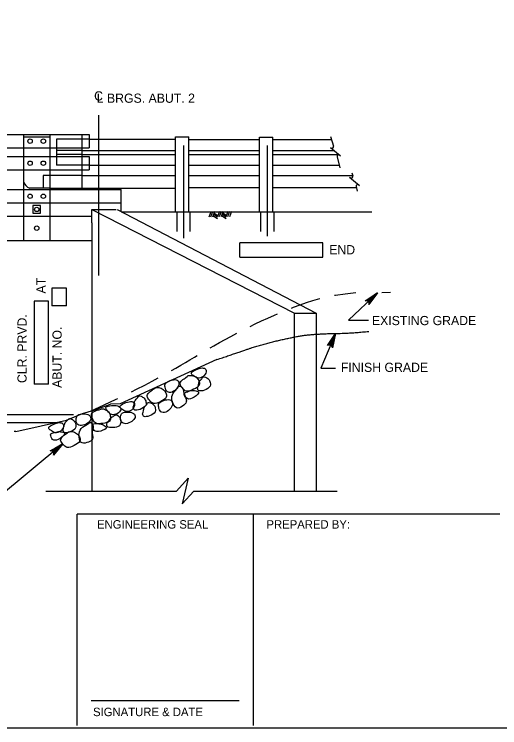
# Model space of a CAD drawing. Extents: x -8 to 75, y -110 to 0.
# Drawn here: x 11.66 to 18.01, y -65.25 to -55.91 of the extents above; entities that cross this region are included whole.
import ezdxf

# ---------------------------------------------------------------- set-up
doc = ezdxf.new("R2010")
doc.units = 0
for name, color, linetype in [('1', 7, 'Continuous'), ('10', 7, 'Continuous'), ('3', 7, 'Continuous'), ('4', 7, 'Continuous'), ('63', 7, 'Continuous'), ('8', 7, 'Continuous')]:
    doc.layers.add(name, color=color, linetype=linetype)

# ---------------------------------------------------------------- blocks, each defined once
blk = doc.blocks.new('F10000')
at = {"layer": '63'}
blk.add_lwpolyline([(-0.03125, -0.03125), (0.03125, -0.03125), (0.03125, 0.03125), (-0.03125, 0.03125)], close=True, dxfattribs=at)

msp = doc.modelspace()

# ---------------------------------------------------------------- linework, layer by layer
at = {"layer": '1'}
msp.add_lwpolyline([(1.75, -65.25), (33.25, -65.25), (33.25, -44.75), (1.75, -44.75)], close=True, dxfattribs=at)
at = {"layer": '3'}
for p, q in [((5.5604, -57.4883), (12.6373, -57.4883)), ((11.7806, -57.4883), (11.7806, -58.8724)), ((12.1266, -57.4883), (12.1266, -58.8724)), ((12.5421, -57.4883), (12.5421, -57.6612)), ((12.6373, -57.4883), (12.6373, -57.6612)), ((11.7806, -57.5171), (12.1266, -57.5171)), ((12.6373, -57.5493), (12.2133, -57.5493)), ((12.2133, -57.5493), (12.2133, -57.8887)), ((12.6373, -57.5493), (13.7701, -57.5493)), ((13.7701, -57.5187), (13.9431, -57.5187)), ((13.7701, -58.4975), (13.7701, -57.5187)), ((13.9431, -58.4975), (13.9431, -57.5187)), ((13.9431, -57.5507), (14.8658, -57.5507)), ((14.8658, -57.5218), (15.0388, -57.5218)), ((14.8658, -58.4975), (14.8658, -57.5218)), ((15.0388, -58.4975), (15.0388, -57.5218)), ((15.0388, -57.5507), (15.8068, -57.5507)), ((15.7952, -57.5147), (15.8358, -57.6407)), ((10.2234, -57.6612), (11.7806, -57.6612)), ((11.7806, -57.6612), (12.1266, -57.6612)), ((12.1266, -57.6612), (12.6373, -57.6612)), ((12.5421, -57.6953), (12.2133, -57.6953)), ((12.5421, -57.6612), (12.5421, -57.7767)), ((12.5421, -57.6953), (13.7701, -57.6953)), ((13.8709, -57.6324), (13.8709, -58.8434)), ((13.9431, -57.6953), (14.8658, -57.6953)), ((14.9667, -57.6324), (14.9667, -58.8182)), ((15.0388, -57.6953), (15.8396, -57.6953)), ((15.7932, -57.6562), (15.9238, -57.7658)), ((10.2234, -57.7767), (11.7806, -57.7767)), ((11.7806, -57.7767), (12.1266, -57.7767)), ((12.1266, -57.7767), (12.6373, -57.7767)), ((12.5421, -57.7473), (12.2133, -57.7473)), ((12.5421, -57.7473), (13.7701, -57.7473)), ((12.5421, -57.7767), (12.5421, -57.9497)), ((12.6373, -57.7767), (12.6373, -57.9497)), ((13.9431, -57.7473), (14.8658, -57.7473)), ((15.0388, -57.7473), (15.9017, -57.7473)), ((15.8805, -57.7794), (15.9167, -57.924)), ((10.2234, -57.9497), (11.7806, -57.9497)), ((11.7806, -57.9497), (12.1266, -57.9497)), ((12.1266, -57.9497), (12.6373, -57.9497)), ((12.6373, -57.8887), (12.2133, -57.8887)), ((12.5421, -57.9497), (12.5421, -58.1882)), ((12.6373, -57.8887), (13.7701, -57.8887)), ((13.9431, -57.8887), (14.8658, -57.8887)), ((15.0388, -57.8887), (15.9078, -57.8887)), ((12.5421, -58.0253), (12.0395, -58.0253)), ((12.0395, -58.0253), (12.0395, -58.1882)), ((12.5421, -58.0253), (13.7701, -58.0253)), ((13.9431, -58.0253), (14.8658, -58.0253)), ((15.0388, -58.0253), (16.0841, -58.0253)), ((16.0427, -58.0451), (16.1733, -58.1547)), ((16.0727, -57.9899), (16.0854, -58.0296)), ((10.2234, -58.2092), (11.7806, -58.2092)), ((11.7806, -58.2092), (12.1266, -58.2092)), ((12.1267, -58.1882), (11.8633, -58.1882)), ((12.1264, -58.1882), (13.7701, -58.1882)), ((12.1266, -58.2092), (13.0586, -58.2092)), ((13.0586, -58.4975), (13.0586, -58.2092)), ((14.8658, -58.1836), (13.9431, -58.1836)), ((16.1339, -58.1836), (15.0388, -58.1836)), ((16.1301, -58.1683), (16.1452, -58.2287)), ((10.2234, -58.3822), (11.7806, -58.3822)), ((11.7806, -58.3822), (12.1266, -58.3822)), ((12.1266, -58.3822), (13.0586, -58.3822)), ((12.6747, -58.6417), (12.6747, -58.4687)), ((12.6747, -58.4687), (15.3228, -59.8239)), ((12.6747, -58.6417), (12.6747, -58.4687)), ((12.6747, -58.4687), (12.9918, -58.4687)), ((13.0032, -58.4687), (15.6082, -59.8239)), ((13.0586, -58.4975), (16.3372, -58.4975)), ((13.7844, -58.4975), (13.7844, -58.757)), ((13.9574, -58.4975), (13.9574, -58.757)), ((14.2294, -58.4975), (14.2027, -58.5677)), ((14.2513, -58.4972), (14.2247, -58.5674)), ((14.2768, -58.4967), (14.2502, -58.567)), ((14.265, -58.5277), (14.3167, -58.5634)), ((14.2715, -58.5105), (14.3231, -58.5463)), ((14.3419, -58.4967), (14.3157, -58.566)), ((14.3638, -58.4966), (14.3376, -58.5656)), ((14.3892, -58.4963), (14.3631, -58.5652)), ((14.3774, -58.5272), (14.429, -58.563)), ((14.3838, -58.5101), (14.4355, -58.5459)), ((14.4543, -58.4963), (14.4281, -58.5656)), ((14.4762, -58.4962), (14.45, -58.5652)), ((14.5016, -58.496), (14.4755, -58.5648)), ((14.8802, -58.4975), (14.8802, -58.757)), ((15.0532, -58.4975), (15.0532, -58.757)), ((10.2234, -58.5552), (11.7806, -58.5552)), ((11.7806, -58.5552), (12.1266, -58.5552)), ((12.1266, -58.5552), (12.6747, -58.5552)), ((14.2582, -58.5456), (14.3182, -58.5872)), ((14.3706, -58.5452), (14.4306, -58.5867)), ((12.6747, -58.6417), (12.6747, -61.1017)), ((5.5232, -58.8724), (12.6747, -58.8724)), ((16.4092, -59.5601), (16.0298, -59.9173)), ((15.3228, -59.8239), (15.6082, -59.8239)), ((15.3228, -60.1378), (15.3228, -59.8239)), ((15.6082, -59.8239), (15.6082, -60.1017)), ((16.0298, -59.9173), (16.2937, -59.9173)), ((15.6082, -60.1017), (15.6082, -62.1527)), ((15.8586, -60.0913), (15.6682, -60.5471)), ((15.3228, -62.1527), (15.3228, -60.1378)), ((14.3088, -60.4333), (13.0453, -61.0127)), ((15.6682, -60.5471), (15.8588, -60.5471)), ((13.0453, -61.0127), (12.9193, -61.0158)), ((12.6747, -61.1017), (12.6747, -62.1527)), ((5.7774, -61.2572), (12.2067, -61.2572)), ((13.7791, -62.1527), (13.9328, -61.9859)), ((13.9328, -61.9859), (13.8558, -62.3197)), ((12.0717, -62.1527), (13.7791, -62.1527)), ((13.8558, -62.3197), (14.0096, -62.1527)), ((14.0096, -62.1527), (15.8827, -62.1527))]:
    msp.add_line(p, q, dxfattribs=at)
for points in [[(16.3073, -59.6289), (16.3343, -59.6576), (16.4068, -59.5622)], [(15.7949, -60.1927), (15.8312, -60.2079), (15.8586, -60.0913)]]:
    msp.add_lwpolyline(points, close=True, dxfattribs=at)
for centre in [(11.8671, -57.5748), (12.0401, -57.5748), (11.8671, -57.8631), (12.0401, -57.8631), (11.867, -58.2957), (12.0401, -58.2957), (11.9536, -58.4681), (11.9536, -58.7132)]:
    msp.add_circle(centre, 0.0288, dxfattribs=at)
for centre, radius, start, end in [((15.8156, -57.6472), 0.0213, 227.85042, 17.85042), ((15.9014, -57.7747), 0.0213, 49.98318, 192.52183), ((15.9014, -57.7748), 0.0213, 49.98318, 49.99719), ((16.0652, -58.036), 0.0213, 227.85042, 17.85042), ((11.8955, -58.0748), 0.1179, 193.19618, 254.16171), ((16.1509, -58.1635), 0.0213, 49.98318, 192.52183), ((16.151, -58.1636), 0.0213, 49.98318, 49.99719), ((11.6599, -61.8326), 0.4593, 87.42134, 90)]:
    msp.add_arc(centre, radius, start, end, dxfattribs=at)
for points, degree in [([(14.3088, -60.4333), (14.62, -60.3259), (14.9059, -60.2327), (15.1917, -60.1629), (15.4618, -60.1105), (15.7158, -60.0931), (16.0573, -60.0872), (16.2956, -60.0639)], 2), ([(13.9835, -60.6266), (13.9931, -60.6369), (14.0278, -60.6591), (14.072, -60.6848), (14.1513, -60.6472), (14.1817, -60.5701), (14.1382, -60.5339), (14.0573, -60.5515), (13.9702, -60.5972), (13.9739, -60.6163), (13.9835, -60.6266)], 3), ([(13.927, -60.6489), (13.9248, -60.6523), (13.9115, -60.6637), (13.848, -60.7003), (13.8163, -60.7577), (13.8564, -60.7997), (13.9045, -60.8648), (14.0076, -60.8247), (14.0964, -60.7682), (14.0745, -60.7043), (14.043, -60.6593), (13.9788, -60.635), (13.9249, -60.6433), (13.9292, -60.6455), (13.927, -60.6489)], 3), ([(14.0683, -60.7665), (14.0657, -60.7786), (14.0536, -60.7933), (14.0597, -60.8422), (14.1134, -60.8489), (14.2292, -60.7989), (14.2254, -60.7287), (14.2049, -60.6847), (14.1545, -60.6564), (14.1283, -60.6552), (14.1164, -60.6797), (14.0695, -60.721), (14.071, -60.7545), (14.0683, -60.7665)], 3), ([(13.6379, -60.7424), (13.6267, -60.7572), (13.6282, -60.7907), (13.6533, -60.8639), (13.727, -60.8693), (13.7969, -60.8043), (13.8248, -60.739), (13.7861, -60.6855), (13.6952, -60.7017), (13.6491, -60.7276), (13.6379, -60.7424)], 3), ([(13.496, -60.8081), (13.4938, -60.8115), (13.4805, -60.8229), (13.417, -60.8597), (13.3852, -60.9169), (13.4254, -60.9589), (13.4735, -61.0241), (13.5766, -60.984), (13.6654, -60.9275), (13.6435, -60.8636), (13.612, -60.8186), (13.5478, -60.7942), (13.4939, -60.8026), (13.4982, -60.8047), (13.496, -60.8081)], 3), ([(13.8107, -60.7811), (13.8052, -60.7847), (13.8007, -60.8031), (13.7103, -60.8954), (13.7203, -60.9839), (13.7762, -61.0873), (13.8641, -61.0468), (13.9206, -60.9866), (13.9017, -60.9318), (13.8717, -60.891), (13.8775, -60.8175), (13.834, -60.7814), (13.8163, -60.7775), (13.8107, -60.7811)], 3), ([(13.9087, -60.8579), (13.8919, -60.8637), (13.8798, -60.8678), (13.9081, -60.9501), (13.9769, -60.9571), (14.1017, -60.8584), (14.028, -60.8373), (13.9805, -60.8332), (13.9255, -60.8521), (13.9087, -60.8579)], 3), ([(13.2273, -61.0183), (13.2247, -61.0303), (13.2126, -61.0449), (13.2187, -61.0939), (13.2724, -61.1006), (13.3882, -61.0507), (13.3844, -60.9804), (13.364, -60.9364), (13.3135, -60.9082), (13.2874, -60.9069), (13.2754, -60.9314), (13.2285, -60.9727), (13.23, -61.0062), (13.2273, -61.0183)], 3), ([(13.5538, -61.0044), (13.5427, -61.0192), (13.5442, -61.0527), (13.5693, -61.1259), (13.6429, -61.1313), (13.7128, -61.0663), (13.7408, -61.001), (13.702, -60.9475), (13.6111, -60.9637), (13.565, -60.9896), (13.5538, -61.0044)], 3), ([(12.86, -61.076), (12.8658, -61.0889), (12.8914, -61.1211), (12.9249, -61.1597), (13.0121, -61.1501), (13.0658, -61.0869), (13.0364, -61.0386), (12.9543, -61.0289), (12.857, -61.0437), (12.8543, -61.0631), (12.86, -61.076)], 3), ([(13.0479, -61.0658), (13.0575, -61.0761), (13.0922, -61.0983), (13.1364, -61.124), (13.2157, -61.0865), (13.2461, -61.0093), (13.2026, -60.9732), (13.1217, -60.9907), (13.0346, -61.0364), (13.0383, -61.0555), (13.0479, -61.0658)], 3), ([(13.35, -61.103), (13.3474, -61.1151), (13.3353, -61.1298), (13.3413, -61.1787), (13.3951, -61.1854), (13.5108, -61.1354), (13.5071, -61.0652), (13.4866, -61.0212), (13.4362, -60.9929), (13.41, -60.9917), (13.3981, -61.0162), (13.3512, -61.0575), (13.3527, -61.091), (13.35, -61.103)], 3), ([(12.4921, -61.158), (12.4767, -61.1684), (12.4672, -61.2007), (12.4672, -61.2779), (12.5352, -61.3069), (12.6223, -61.2682), (12.67, -61.2155), (12.6508, -61.1523), (12.5595, -61.1382), (12.5074, -61.1476), (12.4921, -61.158)], 3), ([(12.7993, -61.0787), (12.7961, -61.0812), (12.7799, -61.0877), (12.7079, -61.1017), (12.6593, -61.1456), (12.6836, -61.1983), (12.7079, -61.2757), (12.8184, -61.2712), (12.9208, -61.2467), (12.9208, -61.179), (12.9057, -61.1262), (12.8529, -61.0824), (12.7992, -61.0727), (12.8026, -61.0762), (12.7993, -61.0787)], 3), ([(13.0727, -61.1337), (13.0573, -61.1441), (13.0478, -61.1763), (13.0478, -61.2536), (13.1158, -61.2826), (13.2029, -61.244), (13.2506, -61.1912), (13.2313, -61.128), (13.1401, -61.1139), (13.088, -61.1233), (13.0727, -61.1337)], 3), ([(12.3099, -61.3131), (12.3073, -61.3251), (12.2952, -61.3397), (12.3012, -61.3887), (12.355, -61.3954), (12.4707, -61.3454), (12.467, -61.2752), (12.4465, -61.2312), (12.3961, -61.2029), (12.3699, -61.2017), (12.358, -61.2263), (12.3111, -61.2675), (12.3126, -61.3011), (12.3099, -61.3131)], 3), ([(12.8948, -61.2359), (12.8884, -61.2464), (12.8722, -61.2563), (12.8621, -61.3047), (12.9107, -61.3284), (13.0364, -61.3188), (13.0557, -61.2512), (13.0506, -61.2028), (13.0121, -61.1597), (12.9878, -61.1501), (12.9685, -61.1694), (12.9107, -61.1932), (12.9012, -61.2254), (12.8948, -61.2359)], 3), ([(12.1179, -61.3422), (12.1275, -61.3526), (12.1623, -61.3747), (12.2065, -61.4003), (12.2858, -61.3629), (12.3161, -61.2857), (12.2726, -61.2496), (12.1917, -61.2671), (12.1046, -61.3128), (12.1083, -61.3319), (12.1179, -61.3422)], 3), ([(12.6499, -61.2559), (12.6435, -61.2575), (12.6334, -61.2734), (12.5178, -61.3313), (12.4986, -61.4183), (12.5178, -61.5343), (12.6141, -61.5246), (12.6871, -61.4859), (12.6871, -61.428), (12.6719, -61.3797), (12.7013, -61.3121), (12.6719, -61.2637), (12.6564, -61.2543), (12.6499, -61.2559)], 3), ([(12.7142, -61.2704), (12.6964, -61.2704), (12.6836, -61.2704), (12.6836, -61.3574), (12.7465, -61.3864), (12.8965, -61.3336), (12.8337, -61.2897), (12.7901, -61.2704), (12.7319, -61.2704), (12.7142, -61.2704)], 3), ([(12.1556, -61.3968), (12.1388, -61.4026), (12.1267, -61.4067), (12.1549, -61.489), (12.2237, -61.496), (12.3485, -61.3973), (12.2748, -61.3763), (12.2273, -61.3722), (12.1723, -61.3911), (12.1556, -61.3968)], 3), ([(12.3649, -61.3839), (12.3627, -61.3873), (12.3494, -61.3987), (12.2859, -61.4354), (12.2542, -61.4927), (12.2943, -61.5347), (12.3424, -61.5999), (12.4455, -61.5598), (12.5344, -61.5033), (12.5124, -61.4393), (12.4809, -61.3944), (12.4168, -61.3701), (12.3628, -61.3783), (12.3672, -61.3806), (12.3649, -61.3839)], 3)]:
    msp.add_open_spline(points, degree=degree, dxfattribs=at)
at = {"layer": '4'}
for p, q in [((12.7609, -57.2338), (12.7609, -59.3328)), ((15.6942, -58.9064), (14.6082, -58.9064)), ((14.6082, -59.0946), (14.6082, -58.9064)), ((15.6942, -59.0946), (15.6942, -58.9064)), ((14.6082, -59.0946), (15.6942, -59.0946)), ((12.1527, -59.4991), (12.1527, -59.729)), ((12.3409, -59.4991), (12.1527, -59.4991)), ((12.3409, -59.729), (12.3409, -59.4991)), ((11.9189, -59.6694), (11.9189, -60.7553)), ((12.1072, -59.6694), (11.9189, -59.6694)), ((12.1072, -60.7553), (12.1072, -59.6694)), ((12.3409, -59.729), (12.1527, -59.729)), ((12.1072, -60.7553), (11.9189, -60.7553)), ((11.1992, -61.1516), (12.4323, -61.1516)), ((12.293, -61.5353), (11.2272, -62.4244)), ((12.4827, -65.2197), (12.4827, -62.4557)), ((18.0107, -62.4557), (12.4827, -62.4557)), ((14.7862, -65.2197), (14.7862, -62.4557)), ((14.6019, -64.8967), (12.6671, -64.8967))]:
    msp.add_line(p, q, dxfattribs=at)
for points in [[(16.4092, -59.5601), (16.2974, -59.7133), (16.3011, -59.6962), (16.2979, -59.6821), (16.2908, -59.6715), (16.2808, -59.6638), (16.2667, -59.6598), (16.2495, -59.6624), (16.4092, -59.5601), (16.2667, -59.6598), (16.2808, -59.6638), (16.4092, -59.5601), (16.2908, -59.6715), (16.2979, -59.6821), (16.4092, -59.5601), (16.3011, -59.6962)], [(15.8586, -60.0913), (15.819, -60.2768), (15.8153, -60.2597), (15.8067, -60.2481), (15.796, -60.2413), (15.7836, -60.2384), (15.7692, -60.2405), (15.7545, -60.2499), (15.8586, -60.0913), (15.7692, -60.2405), (15.7836, -60.2384), (15.8586, -60.0913), (15.796, -60.2413), (15.8067, -60.2481), (15.8586, -60.0913), (15.8153, -60.2597)], [(11.6806, -61.3738), (12.3412, -61.2273), (12.5514, -61.1375), (12.7021, -61.0938), (12.9193, -61.0158)], [(12.293, -61.5353), (12.1723, -61.6816), (12.1769, -61.6647), (12.1746, -61.6504), (12.1683, -61.6394), (12.1586, -61.6312), (12.1448, -61.6263), (12.1275, -61.6279), (12.293, -61.5353), (12.1448, -61.6263), (12.1586, -61.6312), (12.293, -61.5353), (12.1683, -61.6394), (12.1746, -61.6504), (12.293, -61.5353), (12.1769, -61.6647)]]:
    msp.add_lwpolyline(points, dxfattribs=at)
msp.add_lwpolyline([(12.1897, -61.5959), (12.2149, -61.6262), (12.293, -61.5353)], close=True, dxfattribs=at)
at = {"layer": '8'}
for p, q in [((15.9851, -59.5707), (16.1261, -59.5564)), ((16.4646, -59.5564), (16.5777, -59.549)), ((15.5637, -59.6577), (15.6537, -59.6318)), ((15.6537, -59.6318), (15.6554, -59.6314)), ((15.8479, -59.5906), (15.8613, -59.5881)), ((15.8613, -59.5881), (15.9851, -59.5707)), ((15.2832, -59.7593), (15.3133, -59.7474)), ((15.3133, -59.7474), (15.3963, -59.7156)), ((15.3963, -59.7156), (15.479, -59.6856)), ((15.479, -59.6856), (15.5637, -59.6577)), ((15.0612, -59.8517), (15.1013, -59.8345)), ((14.8105, -59.9667), (14.8934, -59.9274)), ((14.8934, -59.9274), (14.9771, -59.889)), ((14.9771, -59.889), (15.0612, -59.8517)), ((14.7438, -59.9992), (14.8105, -59.9667)), ((14.4911, -60.1296), (14.5684, -60.0885)), ((14.2714, -60.251), (14.3422, -60.2112)), ((14.3422, -60.2112), (14.4155, -60.1705)), ((14.4155, -60.1705), (14.4911, -60.1296)), ((14.2236, -60.2784), (14.2714, -60.251)), ((13.9568, -60.435), (14.0161, -60.3998)), ((14.0161, -60.3998), (14.0536, -60.3777)), ((13.8361, -60.5063), (13.8972, -60.4703)), ((13.8972, -60.4703), (13.9568, -60.435)), ((13.7139, -60.5767), (13.7722, -60.5433)), ((13.7722, -60.5433), (13.8361, -60.5063)), ((13.4643, -60.7144), (13.5419, -60.6726)), ((13.2567, -60.8219), (13.3665, -60.7658)), ((13.3665, -60.7658), (13.4643, -60.7144)), ((13.1924, -60.8537), (13.2567, -60.8219)), ((12.8357, -61.0249), (12.9932, -60.9508)), ((12.9932, -60.9508), (13.0156, -60.9401)), ((12.6587, -61.1063), (12.8357, -61.0249))]:
    msp.add_line(p, q, dxfattribs=at)

# ---------------------------------------------------------------- block references
at = {"layer": '3', "xscale": 1.5875015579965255, "yscale": 1.5875015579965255}
msp.add_blockref('F10000', (11.9537, -58.4682), dxfattribs=at)

# ---------------------------------------------------------------- texts
at = {"layer": '10'}
for s, p in [('ENGINEERING SEAL', (12.742, -62.6446)), ('PREPARED BY:', (14.9577, -62.6446)), ('SIGNATURE & DATE', (12.6899, -65.0983))]:
    msp.add_text(s, height=0.110535, dxfattribs=at).set_placement(p)
at = {"layer": '4'}
for s, p in [('C', (12.7038, -57.0423)), ('L BRGS. ABUT. 2', (12.7382, -57.0721)), ('END', (15.7782, -59.0551)), ('EXISTING GRADE', (16.3366, -59.9819)), ('FINISH GRADE', (15.9303, -60.5937))]:
    msp.add_text(s, height=0.12, dxfattribs=at).set_placement(p)
for s, p in [('AT', (12.0694, -59.5677)), ('CLR. PRVD.', (11.8214, -60.7397)), ('ABUT. NO. ', (12.2797, -60.8036))]:
    msp.add_text(s, height=0.12, rotation=90, dxfattribs=at).set_placement(p)

doc.saveas('drawing.dxf')
